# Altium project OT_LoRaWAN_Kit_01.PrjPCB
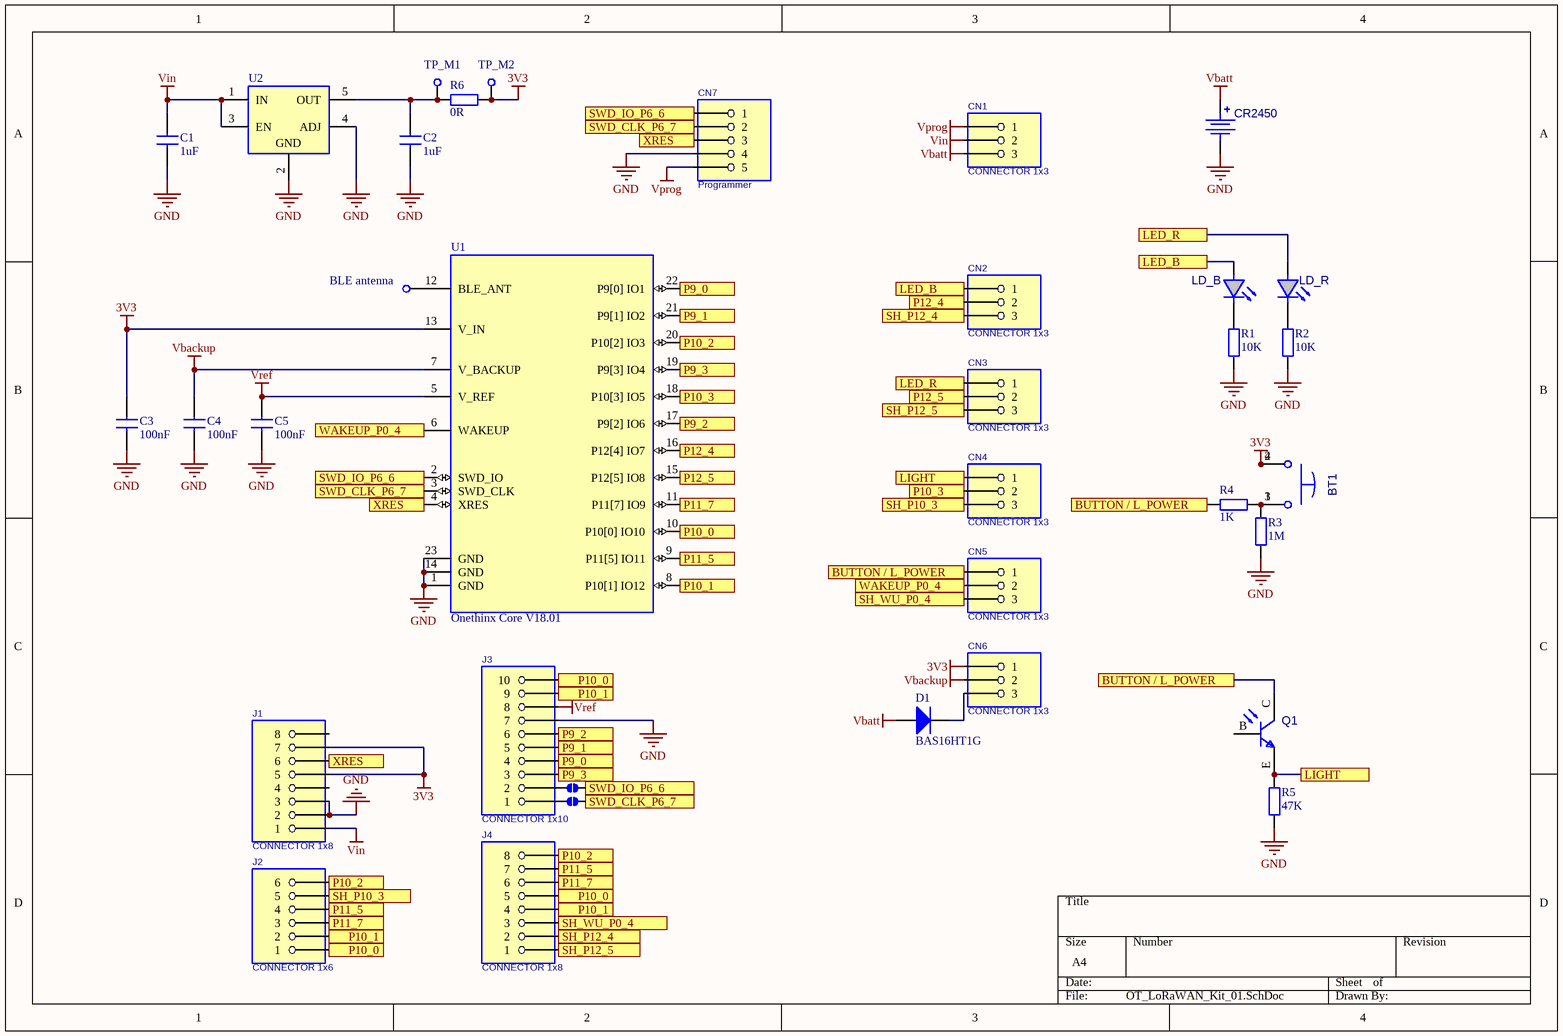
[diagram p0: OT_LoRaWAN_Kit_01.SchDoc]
1 sheet, 35 parts. Net scope: flat (ports and power ports of the same name join across sheets).
Board file: OT_LoRaWAN_Kit_01.PcbDoc

## Sheet OT_LoRaWAN_Kit_01.SchDoc
size A4

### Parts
BT1  BT P0_4  [BUTTON TACT6x6]  (value not drawn)
C1  1uF  [0603C-GENERIC]
C2  1uF  [0603C-GENERIC]
C3  100nF  [0603C-GENERIC]
C4  100nF  [0603C-GENERIC]
C5  100nF  [0603C-GENERIC]
CN1  CONNECTOR 1x3  [HEADER-1X3]
CN2  CONNECTOR 1x3  [HEADER-1X3]
CN3  CONNECTOR 1x3  [HEADER-1X3]
CN4  CONNECTOR 1x3  [HEADER-1X3]
CN5  CONNECTOR 1x3  [HEADER-1X3]
CN6  CONNECTOR 1x3  [HEADER-1X3]
CN7  Programmer  [CON Molex 22053051]
CR2450  BAT  [BATT_2450 clip - TH]  (value not drawn)
D1  BAS16HT1G  [SOD323]
J1  CONNECTOR 1x8  [SOCKET 2.54 1X8 TH]
J2  CONNECTOR 1x6  [SOCKET 2.54 1X6 TH]
J3  CONNECTOR 1x10  [SOCKET 2.54 1X10 TH]
J4  CONNECTOR 1x8  [SOCKET 2.54 1X8 TH]
JMP1  SWD to shield  [SOLDER JUMPER]  (value not drawn)  (no BOM)
JMP2  SWD to shield  [SOLDER JUMPER]  (value not drawn)  (no BOM)
LD_B  LD P12_4  [LED SMD 0603 (1608)]  (value not drawn)
LD_R  LD P12_5  [LED SMD 0603 (1608)]  (value not drawn)
Q1  Q1 P10_3  [PLCC-3_CEB]  (value not drawn)
R1  10K  [0603R-GENERIC]
R2  10K  [0603R-GENERIC]
R3  1M  [0603R-GENERIC]
R4  1K  [0603R-GENERIC]
R5  47K  [0603R-GENERIC]
R6  0R  [0603R-GENERIC]
TP_BLE  BLE antenna  [TestPoint 2mm]
TP_M1  TestPoint  [TestPoint 2mm]  (value not drawn)
TP_M2  TestPoint  [TestPoint 2mm]  (value not drawn)
U1  Onethinx Core V18.01  [OnethinxCore_18_01]
U2  TPS78330DDC  [SOT-23-5]  (value not drawn)

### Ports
BUTTON / L_POWER, LED_B, LED_R, LIGHT, P9_0, P9_1, P9_2, P9_3, P10_0, P10_1, P10_2, P10_3, P11_5, P11_7, P12_4, P12_5, SH_P10_3, SH_P12_4, SH_P12_5, SH_WU_P0_4, SWD_CLK_P6_7, SWD_IO_P6_6, WAKEUP_P0_4, XRES

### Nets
3V3: BT1.2 BT1.4 C3.2 CN6.1 J1.5 J1.7 R6.1 TP_M2.1 U1.13(V_IN)
GND: C1.1 C2.1 C3.1 C4.1 C5.1 CN7.4 CR2450.MINUS(Minus) J1.2 J1.3 J3.7 R1.1 R2.1 R3.1 R5.1 U1.1(GND) U1.14(GND) U1.23(GND) U2.2(GND) U2.4(ADJ)
Vbackup: C4.2 CN6.2 U1.7(V_BACKUP)
Vbatt: CN1.3 CR2450.PLUS(Plus) D1.A
Vin: C1.2 CN1.2 J1.1 U2.1(IN) U2.3(EN)
Vprog: CN1.1 CN7.5
Vref: C5.2 J3.8 U1.5(V_REF)
BUTTON / L_POWER: CN5.1 Q1.C R4.2 ; port BUTTON / L_POWER
LED_B: CN2.1 LD_B.A ; port LED_B
LED_R: CN3.1 LD_R.A ; port LED_R
LIGHT: CN4.1 Q1.E R5.2 ; port LIGHT
P9_0: J3.4 U1.22(P9[0]_IO1) ; port P9_0
P9_1: J3.5 U1.21(P9[1]_IO2) ; port P9_1
P9_2: J3.6 U1.17(P9[2]_IO6) ; port P9_2
P9_3: J3.3 U1.19(P9[3]_IO4) ; port P9_3
P10_0: J2.1 J3.10 J4.5 U1.10(P10[0]_IO10) ; port P10_0
P10_1: J2.2 J3.9 J4.4 U1.8(P10[1]_IO12) ; port P10_1
P10_2: J2.6 J4.8 U1.20(P10[2]_IO3) ; port P10_2
P10_3: CN4.2 U1.18(P10[3]_IO5) ; port P10_3
P11_5: J2.4 J4.7 U1.9(P11[5]_IO11) ; port P11_5
P11_7: J2.3 J4.6 U1.11(P11[7]_IO9) ; port P11_7
P12_4: CN2.2 U1.16(P12[4]_IO7) ; port P12_4
P12_5: CN3.2 U1.15(P12[5]_IO8) ; port P12_5
SH_P10_3: CN4.3 J2.5 ; port SH_P10_3
SH_P12_4: CN2.3 J4.2 ; port SH_P12_4
SH_P12_5: CN3.3 J4.1 ; port SH_P12_5
SH_WU_P0_4: CN5.3 J4.3 ; port SH_WU_P0_4
SWD_CLK_P6_7: CN7.2 JMP2.B U1.3(SWD_CLK) ; port SWD_CLK_P6_7
SWD_IO_P6_6: CN7.1 JMP1.B U1.2(SWD_IO) ; port SWD_IO_P6_6
WAKEUP_P0_4: CN5.2 U1.6(WAKEUP) ; port WAKEUP_P0_4
XRES: CN7.3 J1.6 U1.4(XRES) ; port XRES
NetBT1_1: BT1.1 BT1.3 R3.2 R4.1
NetC2_2: C2.2 R6.2 TP_M1.1 U2.5(OUT)
NetCN6_3: CN6.3 D1.K
NetJ3_1: J3.1 JMP2.A
NetJ3_2: J3.2 JMP1.A
NetLD_B_K: LD_B.K R1.2
NetLD_R_K: LD_R.K R2.2
NetTP_BLE_1: TP_BLE.1 U1.12(BLE_ANT)

Not connected (* = marked no-connect by the designer): J1 4 8; Q1 B

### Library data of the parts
BT1 = SW-TACT: FSM4JH
C1-C5 = CAP: Capacitor
CN1-CN6 = CONNECTOR 1x3: Harwin M20-9990345
CN7 = CONNECTOR 1x5: CON Molex 22053051
CR2450 = BAT: Battery
D1 = Diode
JMP1 = SolderJumper
JMP2 = SolderJumper: Solder Jumper
LD_B = LED: Wurth 150060BS73220
LD_R = LED: Wurth 150060RS75000
Q1 = Phototransistor: Phototransistor Vishay VEMT4700-GS08
R1-R6 = RES: Resistor
TP_BLE TP_M1 TP_M2 = TestPoint: Test Point
U1 = Onethinx_Core_18_01: PSoC Mixed Signal Array
U2 = Voltage Regulator_EN_ADJ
